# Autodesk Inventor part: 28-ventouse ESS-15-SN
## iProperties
Created: 2011-02
Part Number: 28-ventouse ESS-15-SN
Document SubType Name: Modeling
Designer: eric
Density: 1 g/cm^3
Author: eric
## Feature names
1. Base1
